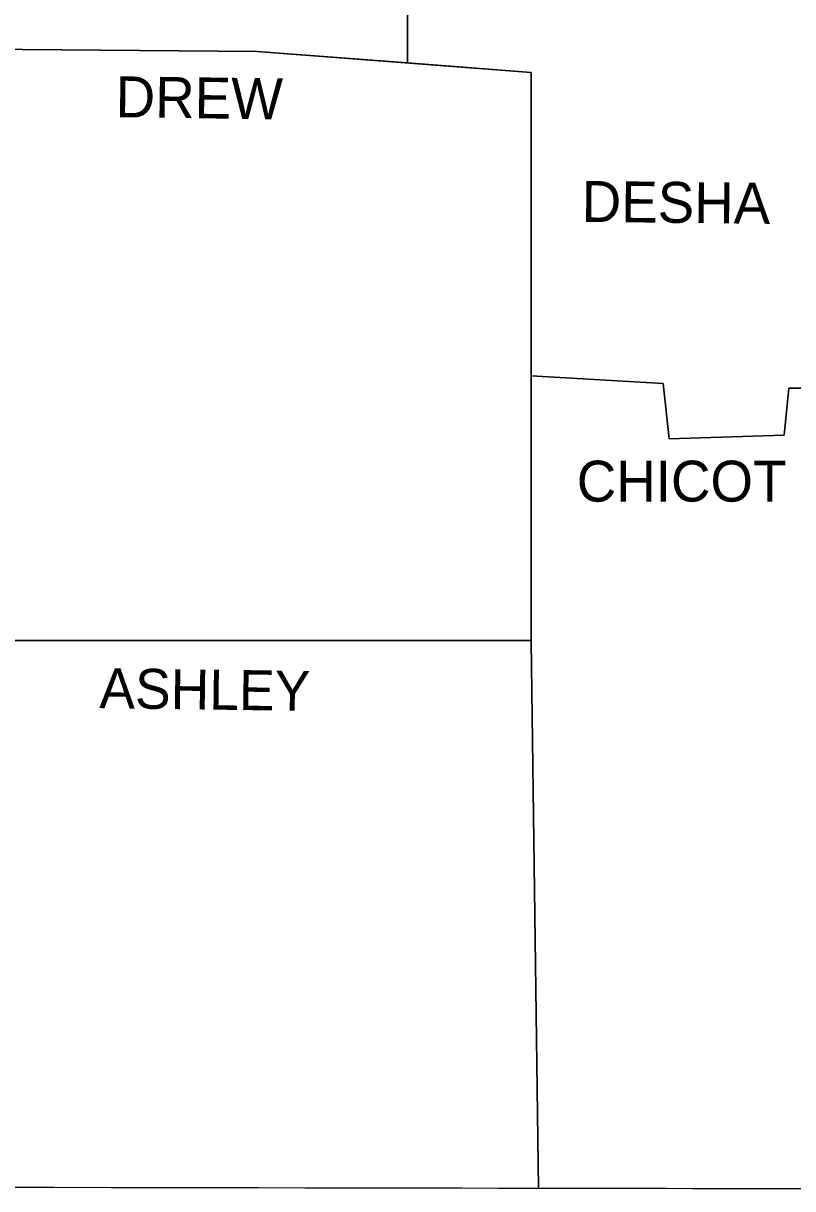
# Model space of a CAD drawing. Extents: x 185 to 5012, y 113 to 2127.
# Drawn here: x 3042.6 to 3121.8, y 1461.2 to 1581 of the extents above; entities that cross this region are included whole.
import ezdxf

# ---------------------------------------------------------------- set-up
doc = ezdxf.new("R2010")
doc.units = 0
for name, color, linetype in [('1', 7, 'Continuous'), ('Default', 7, 'Continuous'), ('R_No Plot', 7, 'Continuous')]:
    doc.layers.add(name, color=color, linetype=linetype)

msp = doc.modelspace()

# ---------------------------------------------------------------- linework, layer by layer
at = {"layer": '1'}
for points in [[(2772.58, 1540.95), (2772.77, 1461.8), (3131.36, 1461.21)], [(2772.59, 1535.97), (2772.77, 1461.8), (3108.79, 1461.25)]]:
    msp.add_lwpolyline(points, dxfattribs=at)
at = {"layer": 'Default'}
for points in [[(3098.19, 1612.87), (3097.02, 1610.23), (3091.83, 1609.74), (3091.54, 1606.22), (3082.24, 1606.22), (3082.14, 1576.96)], [(3030.39, 1578.43), (3066.68, 1578.13), (3094.86, 1575.98)], [(3094.86, 1575.98), (3094.86, 1517.47), (3095.64, 1461.27)], [(3094.86, 1544.8), (3108.46, 1543.99), (3109.05, 1538.31), (3120.89, 1538.7), (3121.38, 1543.5), (3125.04, 1543.5)], [(2772.58, 1540.95), (2772.77, 1461.8), (3131.36, 1461.21)], [(3030.63, 1517.57), (3094.86, 1517.57)]]:
    msp.add_lwpolyline(points, dxfattribs=at)
at = {"layer": 'R_No Plot'}
for p, q in [((3082.24, 1606.22), (3082.14, 1576.96)), ((3082.14, 1576.96), (3094.86, 1575.98)), ((3094.86, 1575.98), (3094.86, 1544.8)), ((3094.86, 1544.8), (3094.86, 1517.57)), ((3094.86, 1544.8), (3108.46, 1543.99)), ((3108.46, 1543.99), (3109.05, 1538.31)), ((3120.89, 1538.7), (3121.38, 1543.5)), ((3121.38, 1543.5), (3125.04, 1543.5)), ((3109.05, 1538.31), (3120.89, 1538.7)), ((3030.63, 1517.57), (3094.86, 1517.57)), ((3094.86, 1517.57), (3030.63, 1517.57)), ((3018.48, 1461.4), (3095.64, 1461.27)), ((3095.64, 1461.27), (3131.36, 1461.21))]:
    msp.add_line(p, q, dxfattribs=at)
for points in [[(3082.14, 1576.96), (3082.24, 1606.22), (3091.54, 1606.22), (3091.83, 1609.74), (3097.02, 1610.23), (3098.19, 1612.87)], [(3030.49, 1578.43), (3066.68, 1578.13), (3082.14, 1576.95)], [(3094.86, 1575.98), (3082.14, 1576.95), (3066.68, 1578.13), (3030.49, 1578.43)], [(3082.14, 1576.95), (3082.14, 1576.96)], [(3094.86, 1517.57), (3094.86, 1544.8), (3094.86, 1575.98)], [(3125.04, 1543.5), (3121.38, 1543.5), (3120.89, 1538.7), (3109.05, 1538.31), (3108.46, 1543.99), (3094.86, 1544.8)], [(3095.64, 1461.27), (3094.86, 1517.47), (3094.86, 1517.57)], [(3094.86, 1517.57), (3094.86, 1517.47), (3095.64, 1461.27)]]:
    msp.add_lwpolyline(points, dxfattribs=at)

# ---------------------------------------------------------------- texts
at = {"layer": 'Default'}
for s, height, rotation, p in [('DREW', 4.207, 359.2258, (3052.11, 1571.38)), ('DESHA', 4.207, 359.3704, (3100.05, 1560.62)), ('ASHLEY', 4.11, 359.2361, (3050.44, 1510.62))]:
    msp.add_text(s, height=height, rotation=rotation, dxfattribs=at).set_placement(p)
msp.add_text('CHICOT', height=4.207, dxfattribs=at).set_placement((3099.56, 1531.85))

doc.saveas('drawing.dxf')
